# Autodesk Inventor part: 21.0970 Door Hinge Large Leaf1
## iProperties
Created: 2007-01
Part Number: 21.0970 Door Hinge Large Leaf1
Document SubType Name: Modeling
Designer: Andy Moles
Material: Aluminum-6061
Density: 2.71 g/cm^3
Author: Andy Moles
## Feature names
1. Extrusion1
2. Extrusion2
3. Hole1
